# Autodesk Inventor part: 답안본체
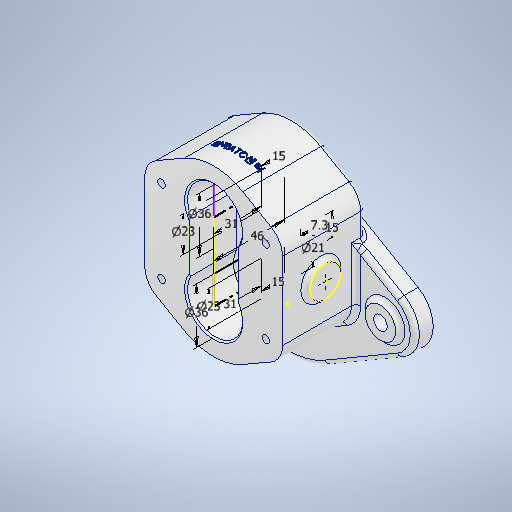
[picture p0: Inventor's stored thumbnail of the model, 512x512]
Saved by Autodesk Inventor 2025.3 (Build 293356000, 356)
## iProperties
Created: 2025-11
Part Number: 답안본체
Material: 알루미늄 6061
Document SubType Name: Modeling
Designer: PC-13
Density: 2.7 g/cm^3
Appearance: 알루미늄 - 평지
Mass: 1253.16 g
Surface Area: 589.991 cm^2
Volume: 464.134 cm^3
Author: PC-13
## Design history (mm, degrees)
sketch "스케치1"
  geometry: L1 (-45, 0)-(-45, 25.238); L2 (-37.5, 38.228)-(-19, 48.909); L3 (19, 48.909)-(37.5, 38.228); L4 (45, 25.238)-(45, 0); L5 (45, 0)-(-45, 0); L6 (-45, 0)-(-45, -25.238); L7 (-37.5, -38.228)-(-19, -48.909); L8 (19, -48.909)-(37.5, -38.228); L9 (45, -25.238)-(45, 0); A1 r 15 centre (-30, 25.238) between (-37.5, 38.228) and (-45, 25.238); A2 r 15 centre (30, 25.238) between (45, 25.238) and (37.5, 38.228); A3 r 15 centre (30, -25.238) between (37.5, -38.228) and (45, -25.238); A4 r 15 centre (-30, -25.238) between (-45, -25.238) and (-37.5, -38.228); A5 r 38 centre (0, 16) between (19, 48.909) and (-19, 48.909); A6 r 38 centre (0, -16) between (-19, -48.909) and (19, -48.909); 8 further points
  constraints: 18 end point, 12 point on circle, 12 point on line, 12 tangent, 6 centre point, 4 equal radius, 3 symmetric about line, 2 midpoint, 2 vertical alignment, 1 equal length, 1 parallel, 1 perpendicular, 1 vertical
  dimensions: "d0" = 90 distance from line of L4 point (-45, 12.619); "d1" = 60 deg angle of L7 L2; "d2" = 60 deg angle of L8 L3; "d3" = 15 radius of A1; "d5" = 38 radius of A5; "d6" = 32 distance of A6.centre A5.centre
extrude "돌출1" new body sketch "스케치1" distance "d7" = 54; taper "d8" = 0 deg
sketch "스케치2"
  geometry: L1 (-73.553, -8.008)-(-26.217, 19.627); L2 (25.786, 19.876)-(74.448, -7.912); L3 (74.448, -42.648)-(25.786, -70.436); L4 (-26.217, -70.187)-(-73.553, -42.552); A1 r 38 centre (0, 16) between (19, 48.909) and (-19, 48.909) reference; A2 r 52 centre (0, -25.28) between (-26.217, 19.627) and (25.786, 19.876); A3 r 15 centre (-30, -25.238) between (-45, -25.238) and (-37.5, -38.228) reference; A4 r 20 centre (-63.469, -25.28) between (-73.553, -8.008) and (-73.553, -42.552); A5 r 20 centre (64.531, -25.28) between (74.448, -42.648) and (74.448, -7.912); A6 r 38 centre (0, -16) between (-19, -48.909) and (19, -48.909) reference; 1 further point
  constraints: 9 point on circle, 8 end point, 8 tangent, 3 centre point, 2 horizontal alignment, 1 vertical alignment
  dimensions: "d77" = 104 diameter of A2; "d81" = 40 diameter of A4; "d82" = 40 diameter of A5; "d83" = 128 distance of A5.centre A4.centre; "d118" = 28.72 distance of point (0, -54) A2.centre
extrude "돌출2" join sketch "스케치2" distance "d35" = 6; taper "d37" = 0 deg; dims "d36" = 6, "d38" = 0
sketch "스케치4"
  geometry: C1 r 25 at (0, -25.28); A1 r 20 centre (-63.469, -25.28) between (-73.553, -8.008) and (-73.553, -42.552) reference; 1 further point
  constraints: 1 centre point, 1 horizontal alignment, 1 vertical alignment
  dimensions: "d39" = 50 diameter of C1
extrude "돌출3" join sketch "스케치4" distance "d41" = 4; taper "d42" = 0 deg
sketch "스케치3"
  geometry: L1 (25.238, 0)-(-25.238, 0) reference; L2 (25.238, 0)-(25.238, -46); L3 (25.238, -46)-(36.738, -46); L4 (36.738, -46)-(36.738, -31); L5 (36.738, -31)-(43.238, -31); L6 (43.238, -31)-(43.238, 0); L7 (-25.238, 0)-(-25.238, -31); L8 (-13.738, -31)-(-7.238, -31); L9 (-7.238, -31)-(-7.238, 0); L10 (-13.738, -31)-(-13.738, -46); L11 (-13.738, -46)-(-14.738, -46); L12 (-25.238, -46)-(-25.238, -31); L13 (-14.738, -46)-(-14.738, -56.7); L14 (-14.738, -56.7)-(-10.238, -56.7); L15 (-25.238, 0)-(-25.238, -54) reference; L16 (-25.238, -46)-(-25.238, -54); L17 (-50.28, -64)-(-0.28, -64) reference; L18 (-25.238, -54)-(-25.238, -64); L19 (-10.238, -64)-(-10.238, -56.7); L20 (43.238, 0)-(25.238, 0); L21 (-7.238, 0)-(-25.238, 0); L22 (-10.238, -64)-(-25.238, -64); L23 (-7.238, 0)-(-25.238, 0); L24 (-10.238, -64)-(-25.238, -64); 2 further points
  constraints: 42 end point, 9 perpendicular, 7 point on line, 4 collinear, 2 vertical, 1 midpoint, 1 parallel
  dimensions: "d18" = 36 diameter of L6 L2; "d19" = 23 diameter of L4 L2; "d21" = 15 distance between parallel lines of L3 L5; "d22" = 36 diameter of L9 L7; "d23" = 31 distance from line of L9.end L5; "d24" = 31 distance between parallel lines of L1 L8; "d25" = 23 diameter of L10 L15; "d26" = 21 diameter of L13 L7; "d28" = 15 distance between parallel lines of L11 L8; "d43" = 7.3 distance between parallel lines of L17 L14; "d44" = 15 distance between parallel lines of L18 L19; "d119" = 46 distance of L2.start L2.end
revolve "회전1" stored, may be unused: angle "d45" = 360 deg
revolve "회전2" stored, may be unused: angle "d46" = 360 deg
chamfer "모따기3" distance "d53" = 1; stored, may be unused: second distance "d54" = 2, angle "d55" = 45 deg
chamfer "모따기4" distance "d56" = 1; stored, may be unused: second distance "d57" = 2, angle "d58" = 45 deg
sketch "스케치5"
  geometry: L1 (-16, 0)-(16, 0); L2 (-16, 16.991)-(-16, -16.991); L3 (16, 16.991)-(16, -16.991); A1 r 18 centre (0, 25.238) between (-16, 16.991) and (16, 16.991) reference; A2 r 18 centre (0, -25.238) between (16, -16.991) and (-16, -16.991) reference; 1 further point
  constraints: 6 end point, 4 point on circle, 2 vertical, 1 horizontal, 1 midpoint
  dimensions: "d59" = 32 distance of L1.start L1.end
extrude "돌출4" cut sketch "스케치5" distance "d60" = 31; taper "d61" = 0 deg
sketch "스케치6"
  geometry: L1 (-34, 27)-(34, 27); L2 (34, 27)-(34, -27); L3 (34, -27)-(-34, -27); L4 (-34, -27)-(-34, 27); 1 further point
  constraints: 8 end point, 2 parallel, 1 horizontal, 1 perpendicular
  dimensions: "d62" = 68 distance of L1.start L1.end; "d63" = 34 distance from line of L4 point (0, 0); "d64" = 54 distance between parallel lines of L3 L1; "d65" = 27 distance from line of point (0, 0) L1
hole "구멍1" sketch "스케치6" at (-34, 27), (34, 27), (34, -27), (-34, -27) diameter "d66" = 4.917; stored, may be unused: countersink angle "d70" = 90 deg, drill point angle "d72" = 118 deg; dims "d67" = 12, "d68" = 4, "d69" = 2, "d71" = 14
sketch "스케치7"
  geometry: L1 (0, 0)-(0, 50.475) reference; C1 r 10 at (25, 25.238); 2 further points
  constraints: 1 centre point, 1 horizontal alignment, 1 midpoint
  dimensions: "d73" = 20 diameter of C1; "d74" = 25 distance from line of C1.centre L1
extrude "돌출5" join sketch "스케치7" distance "d75" = 3; taper "d76" = 0 deg
sketch "스케치8"
  geometry: C1 r 10 at (0, 0) reference; 2 further points
  constraints: 1 coincident
fillet "모깎기1" dims "d85" = 0.3
chamfer "모따기5" distance "d86" = 0.7; stored, may be unused: second distance "d87" = 2, angle "d88" = 30 deg
fillet "모깎기2" dims "d89" = 3
fillet "모깎기3" dims "d90" = 3
fillet "모깎기4" dims "d91" = 3
sketch "스케치9"
  geometry: C1 r 10 at (-64, -25.28); C2 r 10 at (64, -25.28); C3 r 4.5 at (-64.531, -25.28); C4 r 4.5 at (64, -25.28); A1 r 17 centre (-64.531, -25.28) between (-72.961, -10.517) and (-72.961, -40.043) reference; 2 further points
  constraints: 4 centre point, 2 coincident, 2 horizontal alignment, 1 point on circle
  dimensions: "d92" = 20 diameter of C1; "d93" = 20 diameter of C2; "d94" = 128 distance of C1.centre C2.centre; "d95" = 64 horizontal distance of point (0, 0) C1.centre; "d96" = 9 diameter of C3; "d97" = 9 diameter of C4
extrude "돌출6" join sketch "스케치9" distance "d98" = 3; taper "d99" = 0 deg
extrude "돌출7" cut sketch "스케치9" extent not by distance; stored distance "d100" = 0; taper "d101" = 0 deg
chamfer "모따기6" distance "d102" = 1; stored, may be unused: second distance "d103" = 2, angle "d104" = 45 deg
chamfer "모따기7" distance "d105" = 1; stored, may be unused: second distance "d106" = 2, angle "d107" = 45 deg
node "작업 평면3"
sketch "스케치10"
  geometry: L1 (16.592, -18.402)-(-16.592, -18.402); L2 (-16.592, -18.402)-(-16.592, -13.598); L3 (-16.592, -13.598)-(16.592, -13.598); L4 (16.592, -13.598)-(16.592, -18.402); L5 (-37.5, 0)-(-19, 0) reference; L6 (19, 0)-(-19, 0) reference; 3 further points
  constraints: 1 midpoint, 1 vertical alignment, 2 other
  dimensions: "d108" = 2.40163 distance from line of L1 point (0, -16); "d109" = 16.59159 distance from line of L2 point (0, -16); "d110" = 16 distance from line of L5 point (0, -16)
feature "엠보싱1" sketch "스케치10" dims "d0" = 90, "d1" = 60 deg, "d2" = 60 deg, "d3" = 15, "d5" = 38, "d6" = 32, "d7" = 54, "d111" = 0.5, "d112" = 0
fillet "모깎기5" dims "d113" = 3
fillet "모깎기6" dims "d114" = 3
chamfer "모따기8" distance "d115" = 1; stored, may be unused: second distance "d116" = 2, angle "d117" = 45 deg
node "솔리드1"
mirror "미러1"
feature "A9D066F2-1C7D-4E18-AEED-F7BC21143FA4" dims "d66" = 4.917, "d67" = 12, "d68" = 4, "d69" = 2, "d70" = 90 deg, "d71" = 14, "d72" = 118 deg
other parameters: "d14" = 104, "d30" = 104
